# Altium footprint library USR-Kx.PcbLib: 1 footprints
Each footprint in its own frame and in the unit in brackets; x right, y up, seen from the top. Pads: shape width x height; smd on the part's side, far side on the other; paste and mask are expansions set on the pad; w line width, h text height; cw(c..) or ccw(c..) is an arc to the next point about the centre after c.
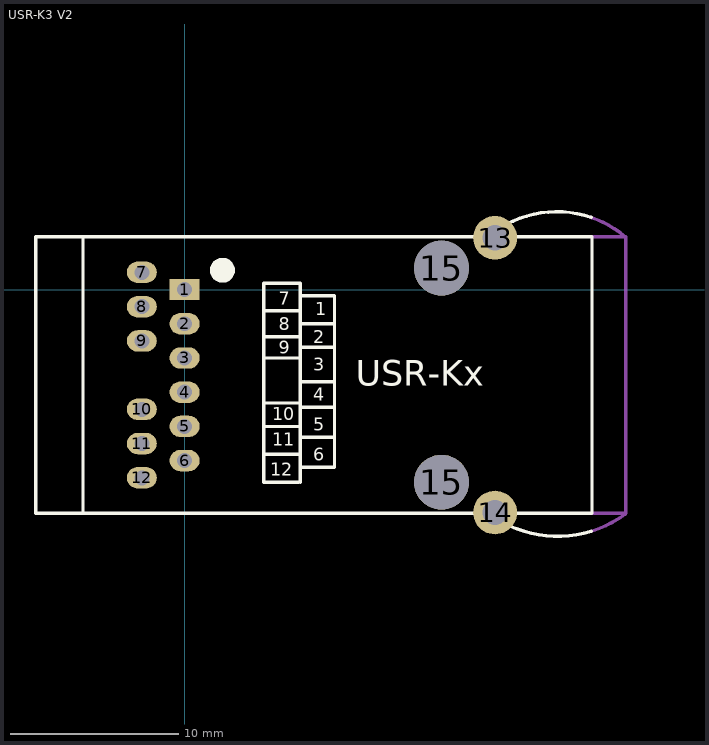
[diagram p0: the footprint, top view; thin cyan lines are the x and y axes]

## USR-K3 V2 [mil]
pads (16):
  rect 70x50 hole 35 mask+2: 1(0,0)
  oval 70x50 hole 35 mask+2: 2(0,-79.92) 3(0,-159.84) 4(0,-239.76) 5(0,-319.69) 6(0,-399.61) 7(-100,40.16) 8(-100,-40.16) 9(-100,-120.08) 10(-100,-279.92) 11(-100,-359.84) 12(-100,-439.76)
  round 102.36 hole 59.06 mask+2: 13(725.18,120.85) 14(725.18,-520.88)
  round 127.95 hole 127.95 unplated: 15(599.98,-450.02) 15(599.98,49.98)
Top Overlay:
  circle w30: c88.46,45 r14.14
  lines w7.99: -237.42,-522.85 -237.42,122.82 ; 185,-385 265,-385 ; 185,-320 270,-320 ; 185,-265 265,-265 ; 185,-160 270,-160 ; 185,-110 265,-110 ; 185,-50 265,-50 ; 265,-450 185,-450 185,15 270,15 270,-450 ; 270,-415 350,-415 350,-15 270,-15 ; 270.01,-345 345.01,-345 ; 270,-275 350,-275 ; 270,-215 350,-215 ; 270,-135 345,-135 ; 270,-80 345,-80 ; 714.1,-525.56 ccw(c871.17,-308.76) 949.87,-564.65 ; 723.24,134.16 cw(c869.46,-66.2) 949.81,168.46 ; 951.56,-522.85 951.56,122.82
  lines w8: 951.56,-522.85 -347.65,-522.85 -347.65,122.82 951.56,122.82
  text "1" at 305,-60 h30
  text "2" at 300,-125 h30
  text "3" at 300,-190 h30
  text "4" at 300,-260 h30
  text "5" at 300,-330 h30
  text "7" at 220,-35 h30
  text "8" at 220,-95 h30
  text "9" at 220,-150 h30
  text "10" at 205,-305 h30
  text "11" at 205,-365 h30
  text "12" at 200,-435 h30
  text "6" at 300,-400 h30
  text "USR-Kx" at 400,-225 h60
Mechanical 13:
  lines w7.99: 947.7,169.11 cw(c869.77,-66.36) 1029.98,122.98 ; 951.56,-522.85 1030.3,-522.85 ; 951.56,122.82 1030.3,122.82 ; 951.98,-563.99 ccw(c871.17,-308.76) 1028.98,-525.02
  lines w8: 1030.32,-522.85 1030.3,122.82
  text "2mm" at 975,-150 h30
